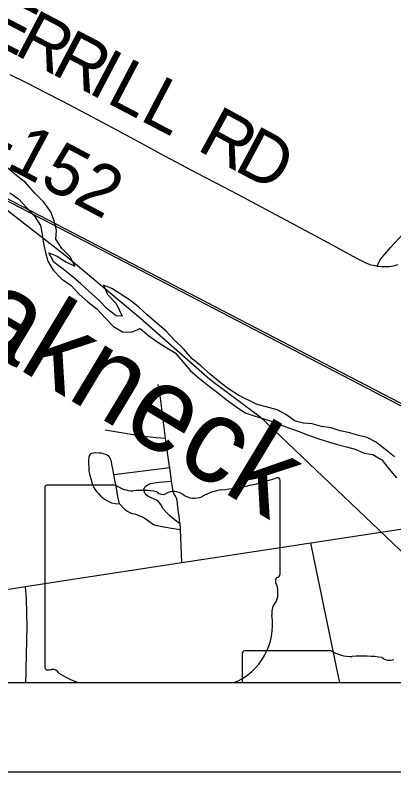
# Model space of a CAD drawing. Extents: x 0 to 34, y 0 to 22.
# Drawn here: x 3.593 to 4.018, y 14 to 14.848 of the extents above; entities that cross this region are included whole.
import ezdxf

# ---------------------------------------------------------------- set-up
doc = ezdxf.new("R2010")
doc.units = 0
for name, color, linetype in [('Default', 7, 'Continuous'), ('GM_X_Corporation', 7, 'Continuous'), ('GM_X_Minor_River', 7, 'Continuous'), ('GM_X_Minor_River_Text', 7, 'Continuous'), ('GM_X_Rail_Line', 7, 'Continuous'), ('GM_X_State_Location', 7, 'Continuous'), ('GM_X_State_Route', 7, 'Continuous'), ('GM_X_Township_Road', 7, 'Continuous'), ('GM_X_Township_Road_Text', 7, 'Continuous'), ('SH_Data', 7, 'Continuous')]:
    doc.layers.add(name, color=color, linetype=linetype)

msp = doc.modelspace()

# ---------------------------------------------------------------- linework, layer by layer
at = {"layer": 'Default'}
for p, q in [((3.7062, 14.32152), (3.62893, 14.32152)), ((3.62639, 14.31805), (3.62639, 14.11798)), ((3.94727, 14.13569), (3.85068, 14.13569)), ((3.6637, 14.1), (3.83843, 14.1))]:
    msp.add_line(p, q, dxfattribs=at)
for points in [[(3.89004, 14.22182), (3.89003, 14.22182), (3.89006, 14.2218), (3.89006, 14.32667)], [(3.8475, 14.13222), (3.8475, 14.1), (4.17708, 14.1), (4.17708, 14.14083)]]:
    msp.add_lwpolyline(points, dxfattribs=at)
for centre, radius, start, end in [((3.79614, 14.59436), 0.27962, 275.84447, 288.90645), ((3.88713, 14.32692), 0.00294, 355.09784, 97.73796), ((3.62941, 14.31851), 0.00305, 98.97798, 188.59666), ((3.72459, 14.34476), 0.02963, 231.64044, 271.11173), ((3.73441, 14.20917), 0.10636, 80.48669, 94.98831), ((3.75856, 14.31954), 0.00855, 219.79206, 297.10237), ((3.77111, 14.29641), 0.01777, 54.46671, 119.14113), ((3.79405, 14.32814), 0.02138, 233.85619, 294.82819), ((3.8318, 14.2604), 0.05625, 97.3462, 120.76885), ((3.88938, 14.21411), 0.00454, 107.94398, 210.33697), ((3.88693, 14.22139), 0.00314, 289.60381, 7.73413), ((3.86048, 14.20088), 0.02727, 340.03296, 23.64957), ((3.90057, 14.17799), 0.01984, 136.8065, 186.92959), ((3.8118, 14.16467), 0.06994, 292.37973, 8.98584), ((3.62944, 14.11752), 0.00308, 171.49107, 258.30654), ((3.62991, 14.138), 0.02352, 267.33899, 280.60386), ((3.63472, 14.10641), 0.00848, 29.74838, 93.27175), ((3.74178, 14.28621), 0.20192, 240.41292, 247.25165)]:
    msp.add_arc(centre, radius, start, end, dxfattribs=at)
for centre, major_axis, start_param, end_param in [((3.85127, 14.13267), (0.00382, 0), 1.727492, 3.291633), ((3.97025, 14.15892), (0.03703, 0), 4.042888, 4.731792), ((3.98253, 14.02334), (0.13295, 0), 1.404758, 1.657859), ((4.01271, 14.13371), (0.01068, 0), 3.836095, 5.185415)]:
    msp.add_ellipse(centre, major_axis=major_axis, ratio=0.8, start_param=start_param, end_param=end_param, dxfattribs=at)
at = {"layer": 'GM_X_Corporation'}
msp.add_lwpolyline([(4.71799, 17.49624), (3.7119, 17.4934), (3.58006, 17.49243), (3.4708, 17.4915), (3.04564, 17.48944), (2.63524, 17.49292), (2.58119, 17.49248), (2.14492, 17.48819), (2.1, 17.48755), (2.1, 14.1), (5.03982, 14.1)], dxfattribs=at)
at = {"layer": 'GM_X_Minor_River'}
for points in [[(4.01843, 14.35306), (4.007, 14.36207), (3.9971, 14.36996), (3.9876, 14.37482), (3.97812, 14.37702), (3.96826, 14.37998), (3.95726, 14.38216), (3.9474, 14.3855), (3.93641, 14.38731), (3.92617, 14.39027), (3.91632, 14.39095), (3.90684, 14.39315), (3.89656, 14.40065), (3.88668, 14.40589), (3.87454, 14.40921), (3.86431, 14.41178), (3.84379, 14.42186), (3.83238, 14.42936), (3.82286, 14.43649), (3.81219, 14.44551), (3.80114, 14.45528), (3.79162, 14.46317), (3.78207, 14.47372), (3.77178, 14.48388), (3.76223, 14.49443), (3.75233, 14.50269), (3.74128, 14.51247), (3.73137, 14.52111), (3.72147, 14.529), (3.70169, 14.54174), (3.6922, 14.54546), (3.69682, 14.53526), (3.70636, 14.52509), (3.71301, 14.51077), (3.70647, 14.51106), (3.69657, 14.51857), (3.68703, 14.52873), (3.67636, 14.53851), (3.66644, 14.54754), (3.65654, 14.55618), (3.64702, 14.56332), (3.63674, 14.5712), (3.63098, 14.58178), (3.64047, 14.57806), (3.64998, 14.57168), (3.66024, 14.56683), (3.65524, 14.57703), (3.6457, 14.58682), (3.63881, 14.59701), (3.63949, 14.60687), (3.63714, 14.61785), (3.63328, 14.62769), (3.62524, 14.63862), (3.61532, 14.64879), (3.60501, 14.66084), (3.59512, 14.66797), (3.58521, 14.67662)], [(3.58732, 14.64895), (3.59683, 14.6422), (3.60637, 14.63241), (3.61515, 14.62262), (3.62166, 14.61243), (3.62363, 14.60258), (3.62484, 14.59235), (3.62719, 14.58213), (3.62992, 14.57229), (3.63567, 14.56247), (3.64521, 14.55268)], [(3.64521, 14.55268), (3.65587, 14.54518), (3.66502, 14.53539), (3.67455, 14.52674), (3.68483, 14.51886), (3.69399, 14.50907), (3.70353, 14.49928), (3.71342, 14.49329), (3.72364, 14.49299), (3.73345, 14.49686), (3.74297, 14.48859), (3.75325, 14.48184), (3.76314, 14.47547), (3.77264, 14.46985), (3.78143, 14.4593), (3.78983, 14.44951), (3.79974, 14.44086), (3.80926, 14.43335), (3.81992, 14.42509), (3.82982, 14.41758), (3.84048, 14.4097), (3.85113, 14.40257), (3.861, 14.39924), (3.87086, 14.39628), (3.88111, 14.39257), (3.8906, 14.38885), (3.90047, 14.38513), (3.91033, 14.3818), (3.92096, 14.37771), (3.93121, 14.374), (3.94183, 14.37066), (3.95283, 14.36734), (3.96459, 14.3644), (3.97407, 14.36182), (3.98433, 14.35734), (3.99418, 14.35591), (4.00407, 14.34991), (4.01247, 14.33936), (4.0205, 14.32956)]]:
    msp.add_lwpolyline(points, dxfattribs=at)
at = {"layer": 'GM_X_Rail_Line'}
for points in [[(4.59399, 14.11583), (4.5467, 14.13137), (4.50292, 14.15115), (4.4554, 14.17333), (4.41289, 14.19637), (4.03238, 14.40668), (3.56218, 14.65114), (3.16185, 14.86779), (3.02758, 14.94055)], [(4.59474, 14.11804), (4.54755, 14.13355), (4.5039, 14.15327), (4.45646, 14.17541), (4.41402, 14.19842), (4.03349, 14.40874), (3.56328, 14.6532), (3.16297, 14.86984), (3.0287, 14.9426)], [(3.0723, 14.82989), (3.09009, 14.80759), (3.10587, 14.79222), (3.15966, 14.77236), (3.21627, 14.75802), (3.24255, 14.75709), (3.27018, 14.75131), (3.2929, 14.73934), (3.33693, 14.70988), (3.43283, 14.67996), (3.53363, 14.65553), (3.58392, 14.63017), (3.64919, 14.57907), (3.73367, 14.50841), (3.81194, 14.43989), (3.86761, 14.39787), (4.07922, 14.19645), (4.13242, 14.12472), (4.14803, 14.1)]]:
    msp.add_lwpolyline(points, dxfattribs=at)
at = {"layer": 'GM_X_State_Route'}
for points in [[(3.92447, 14.25672), (4.02983, 14.27275), (4.04857, 14.2756)], [(3.47992, 14.18794), (3.52862, 14.19566), (3.60478, 14.20772), (3.64812, 14.21469), (3.78017, 14.23478), (3.92447, 14.25672)], [(3.9569, 14.1), (3.95425, 14.11215), (3.92784, 14.24037), (3.92447, 14.25672)]]:
    msp.add_lwpolyline(points, dxfattribs=at)
at = {"layer": 'GM_X_Township_Road'}
for p, q in [((3.70379, 14.33329), (3.76641, 14.34104)), ((3.60538, 14.1), (3.60564, 14.11134))]:
    msp.add_line(p, q, dxfattribs=at)
for points in [[(3.58746, 14.7818), (3.6063, 14.77227), (3.62737, 14.76162), (3.64556, 14.75228), (3.67945, 14.7343), (3.70737, 14.71949), (3.73183, 14.7063), (3.76077, 14.69066), (3.79724, 14.67129), (3.82748, 14.65547), (3.84935, 14.64371), (3.85862, 14.63891), (3.92896, 14.60127), (3.95663, 14.58624), (3.97582, 14.57586), (3.98534, 14.57106), (3.98876, 14.56951), (3.99176, 14.56849), (3.99407, 14.56789), (3.99622, 14.56746), (3.99904, 14.56694), (4.00307, 14.56643), (4.00667, 14.56634), (4.00976, 14.56642), (4.01287, 14.56667), (4.01705, 14.56731), (4.02236, 14.56862)], [(3.99904, 14.56694), (4.00045, 14.57029), (4.00114, 14.57158), (4.00194, 14.57307), (4.00276, 14.57435), (4.00373, 14.57586), (4.00742, 14.58044), (4.01374, 14.58761), (4.02763, 14.60257)], [(3.78017, 14.23478), (3.77973, 14.24426), (3.77848, 14.27132), (3.77843, 14.27247), (3.77802, 14.27789), (3.77793, 14.27896), (3.77711, 14.28628), (3.77604, 14.29326), (3.77466, 14.30405), (3.774, 14.30668), (3.77301, 14.30907), (3.77163, 14.31099), (3.77088, 14.31211), (3.77042, 14.3134), (3.76951, 14.31924), (3.7686, 14.32571), (3.76641, 14.34104), (3.76626, 14.34212), (3.76166, 14.37389), (3.75533, 14.42487), (3.75346, 14.43417)], [(3.69421, 14.38349), (3.73462, 14.3768), (3.75129, 14.37468), (3.76166, 14.37389)], [(3.77848, 14.27132), (3.7684, 14.27298), (3.75985, 14.27439), (3.75241, 14.27562), (3.74871, 14.27682), (3.74697, 14.27776), (3.74295, 14.28083), (3.73997, 14.28298), (3.73584, 14.28552), (3.73135, 14.28732), (3.72863, 14.28843), (3.72693, 14.28892), (3.72517, 14.2894), (3.72285, 14.29008), (3.72057, 14.29097), (3.71843, 14.29213), (3.71645, 14.29363), (3.71017, 14.30045), (3.70848, 14.30851), (3.70626, 14.32008), (3.7049, 14.32728), (3.70418, 14.33142), (3.70379, 14.33329), (3.70344, 14.33505), (3.70255, 14.33982), (3.70206, 14.34293), (3.70079, 14.34895), (3.6998, 14.35125), (3.69918, 14.3523), (3.69854, 14.35315), (3.69773, 14.35394), (3.69623, 14.355), (3.69457, 14.35581), (3.69252, 14.35651), (3.68956, 14.35709), (3.68726, 14.35734), (3.68315, 14.35748), (3.68117, 14.35743), (3.67879, 14.35693), (3.67747, 14.35619), (3.6764, 14.35487), (3.67566, 14.3529), (3.67533, 14.34994), (3.67525, 14.34665), (3.67563, 14.3402), (3.67599, 14.3372), (3.67689, 14.33275), (3.67837, 14.32732), (3.67952, 14.3233), (3.68067, 14.32009), (3.68239, 14.31688), (3.68444, 14.31424), (3.6865, 14.31186), (3.68913, 14.30898), (3.69348, 14.30552), (3.69743, 14.3033), (3.70121, 14.30173), (3.70525, 14.30091), (3.71017, 14.30045)], [(3.77802, 14.27789), (3.7718, 14.28254), (3.76607, 14.28726), (3.7619, 14.29136), (3.75886, 14.29525), (3.75713, 14.29852), (3.75547, 14.30114), (3.75384, 14.30301), (3.7524, 14.30418), (3.75022, 14.30535), (3.74556, 14.30711), (3.7434, 14.30822), (3.74199, 14.3092), (3.74048, 14.31025), (3.73961, 14.31112), (3.73854, 14.31256), (3.73801, 14.31353), (3.7375, 14.31568), (3.73762, 14.31689), (3.73801, 14.31807), (3.73865, 14.31913), (3.73993, 14.32046), (3.74198, 14.32182), (3.74506, 14.32306), (3.74942, 14.32413), (3.75476, 14.32478), (3.7686, 14.32571)], [(3.60564, 14.11134), (3.60576, 14.11637), (3.60645, 14.1472), (3.6065, 14.15305), (3.60654, 14.15814), (3.60629, 14.18215), (3.60608, 14.19018), (3.6059, 14.19389), (3.60555, 14.19895), (3.60478, 14.20772)]]:
    msp.add_lwpolyline(points, dxfattribs=at)
at = {"layer": 'SH_Data'}
for p, q in [((2.1, 14.1), (8.9, 14.1)), ((2, 14), (9, 14))]:
    msp.add_line(p, q, dxfattribs=at)

# ---------------------------------------------------------------- texts
at = {"layer": 'GM_X_Minor_River_Text'}
msp.add_text('Breakneck', height=0.09474, rotation=328.97393, dxfattribs=at).set_placement((3.36557, 14.59063))
at = {"layer": 'GM_X_State_Location'}
for s, p in [('s', (3.75525, 14.20472)), ('r', (3.75524, 14.20472))]:
    msp.add_text(s, height=0.000189, dxfattribs=at).set_placement(p)
msp.add_text('59', height=0.000189, rotation=0.00001, dxfattribs=at).set_placement((3.70756, 14.19094))
at = {"layer": 'GM_X_Township_Road_Text'}
for s, height, rotation, p in [('E', 0.05682, 332.31001, (3.55285, 14.82511)), ('R', 0.05682, 332.32255, (3.5905, 14.80536)), ('R', 0.05682, 332.31781, (3.63182, 14.78368)), ('I', 0.05682, 332.32694, (3.67316, 14.76199)), ('L', 0.05682, 332.31751, (3.69382, 14.75116)), ('L', 0.05682, 332.31751, (3.73145, 14.73141)), ('T-152', 0.056818, 332.02611, (3.51833, 14.71199)), ('R', 0.05682, 331.39764, (3.79543, 14.69799)), ('D', 0.05682, 331.96233, (3.83693, 14.67536))]:
    msp.add_text(s, height=height, rotation=rotation, dxfattribs=at).set_placement(p)

doc.saveas('drawing.dxf')
